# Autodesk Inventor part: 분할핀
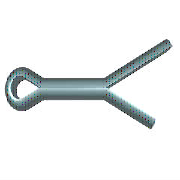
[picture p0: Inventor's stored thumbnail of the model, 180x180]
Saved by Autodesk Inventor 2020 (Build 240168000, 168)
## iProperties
IsCustomPart: 1
Created: 2012-02
Part Number: 분할핀
Material: 강철
Description: 분할 핀
Document SubType Name: Modeling
Standard: ISO 1234
Designer: mdu-01
Standard Revision: Second edition 1997-11-01
Standards Organization: ISO
Language: ko-KR
Size Designation: 2 x 14
Categories: <MemberInstance><Categories><Category DisplayName="조임쇠" InternalName="e4da775c-781d-43d5-af7c-5136215cf5a6" Mnemonic="FSTN"><Category DisplayName="핀" InternalNa
Density: 7.85 g/cm^3
Appearance: 파란색 - 벽 페인트 - 광택
Mass: 0.431632 g
Surface Area: 1.66196 cm^2
Volume: 0.0549849 cm^3
Author: mdu-01
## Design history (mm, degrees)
sketch "스케치1"
  geometry: L1 (0, 0.9)-(8, 0.9); L2 (0, -0.9)-(8, -0.9); L3 (8, 0.9)-(14, 3.199); L4 (14, 3.199)-(14.301, 2.414); L5 (14.301, 2.414)-(8, 0); L6 (8, 0)-(16.801, -3.372); L7 (16.801, -3.372)-(16.5, -4.157); L8 (16.5, -4.157)-(8, -0.9); L9 (0, 0)-(-1.832, -0.821); L10 (0, 0)-(-1.832, 0.821); L11 (0, 0.9)-(0, -0.9); L12 (0, 0.9)-(-1.384, 1.604); L13 (0, -0.9)-(-1.384, -1.604); L14 (-4, 0)-(8, 0); L15 (8, 0.9)-(8, -0.9); A1 r 1.8 centre (-2.2, 0) between (-1.384, 1.604) and (-1.384, -1.604); A2 r 0.9 centre (-2.2, 0) between (-1.832, 0.821) and (-1.832, -0.821); 1 further point
  constraints: 30 end point, 5 point on circle, 4 parallel, 4 perpendicular, 4 point on line, 4 tangent, 2 centre point, 2 midpoint, 1 coincident, 1 horizontal
  dimensions: "d0" = 8 distance of L1.start L1.end (= MSIAB); "d1" = 14 horizontal distance of L1.start L3.end (= SNLG); "d2" = 159.037 deg angle of L1 L3; "d3" = 159.037 deg angle of L2 L8; "d4" = 2.5 horizontal distance of L3.end L7.end (= LGDIF); "d5" = 0.9 radius of A2 (= -0.5 x SNND1 + 0.5 x KBR); "d6" = 1.8 radius of A1 (= 0.5 x KBR); "d7" = 0.9 distance from line of L1 L9.start (= 0.5 x SNND1); "d8" = 0.9 distance between parallel lines of L2 L14 (= 0.5 x SNND1); "d9" = 2.2 distance from line of L11 A1.centre (= KOL - 0.5 x KBR)
extrude "본체" new body sketch "스케치1" stored distance "d10" = 1.8 (= SNND1); taper "d11" = 0 deg
workaxis "Work Axis1"
workplane "Work Plane1"
body "Solid1"
fillet "모깎기" dims "d12" = 0.72 (= 0.4 x SNND1)
node "작업 평면2"
other parameters: "SNND" = 2 [user parameter], "SNLG" = 14 [user parameter; used in 1 equation term], "SNND1" = 1.8 [user parameter; used in 5 equation terms], "KBR" = 3.6 [user parameter; used in 3 equation terms], "KOL" = 4 [user parameter; used in 1 equation term], "LGDIF" = 2.5 [user parameter; used in 1 equation term], "MSIAB" = 8 [user parameter; used in 1 equation term], "d15" = 0, "d16" = 0, "d17" = 0, "NNDMAX" = 9 [user parameter], "DSH" = 4 [user parameter], "NNDMIN" = 7 [user parameter]
